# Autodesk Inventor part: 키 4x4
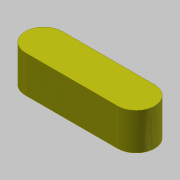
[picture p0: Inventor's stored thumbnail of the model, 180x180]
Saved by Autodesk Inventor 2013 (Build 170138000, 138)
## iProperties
Created: 2018-09
Part Number: 키 4x4
Document SubType Name: Modeling
Density: 7.86 g/cm^3
Material: 강철, 연강
Mass: 1.65269 g
Surface Area: 2.35398 cm^2
Volume: 0.210265 cm^3
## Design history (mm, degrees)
sketch "스케치1"
  geometry: L1 (-5, -2)-(5, -2); L2 (5, 2)-(-5, 2); A1 r 2 centre (5, 0) between (5, -2) and (5, 2); A2 r 2 centre (-5, 0) between (-5, 2) and (-5, -2); 2 further points
  constraints: 4 end point, 4 point on circle, 4 tangent, 2 centre point, 1 horizontal, 1 horizontal alignment, 1 midpoint, 1 parallel, 1 vertical alignment
  dimensions: "d0" = 4 distance between parallel lines of L1 L2; "d1" = 14 dimension on A1 A2
extrude "돌출1" new body sketch "스케치1" stored distance "d2" = 4; taper "d3" = 0 deg
node "솔리드1"
